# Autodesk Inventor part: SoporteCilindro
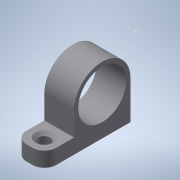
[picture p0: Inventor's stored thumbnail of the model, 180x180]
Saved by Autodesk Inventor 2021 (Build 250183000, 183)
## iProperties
Created: 2021-02
Part Number: SoporteCilindro
Material: Genérico
Document SubType Name: Modeling
Designer: ATOUZA
Density: 1 g/cm^3
Appearance: Valor por defecto
Author: ATOUZA
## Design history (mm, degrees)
sketch "Boceto1"
  geometry: L1 (4.21, 9.241)-(7.675, 15.241) reference; L2 (-2.718, 9.241)-(4.21, 9.241) reference; L3 (-9.646, 9.241)-(-2.718, 9.241) reference; L4 (-13.11, 15.241)-(-9.646, 9.241) reference; L5 (-16.574, 21.241)-(-13.11, 15.241) reference; L6 (-13.11, 27.241)-(-16.574, 21.241) reference; L7 (-9.646, 33.241)-(-13.11, 27.241) reference; L8 (-2.718, 33.241)-(-9.646, 33.241) reference; L9 (4.21, 33.241)-(-2.718, 33.241) reference; L10 (7.675, 27.241)-(4.21, 33.241) reference; L11 (11.139, 21.241)-(7.675, 27.241) reference; L12 (7.675, 15.241)-(11.139, 21.241) reference; L13 (-13.568, 35.333)-(-13.568, 39.333) reference; L14 (-15.568, 135.266)-(-15.568, 5.822); L15 (-2.718, 30.741)-(-15.568, 30.741); L16 (-2.718, 11.741)-(-15.568, 11.741); L17 (-15.568, 30.741)-(-15.568, 11.741); C1 r 8 at (-2.718, 21.241) reference; C2 r 3 at (-2.718, 21.241) reference; C3 r 3 at (-2.718, 21.241); C4 r 8.1 at (-2.718, 21.241); A1 r 9.5 centre (-2.718, 21.241) between (-2.718, 11.741) and (-2.718, 30.741); 1 further point
  constraints: 8 end point, 3 centre point, 3 coincident, 2 perpendicular, 2 point on circle, 2 point on line, 2 tangent, 2 vertical, 1 concentric
  dimensions: "d0" = 16.2 diameter of C4; "d1" = 19 diameter of A1
extrude "Extrusión1" new body sketch "Boceto1" distance "d2" = 10; taper "d3" = 0 deg
sketch "Boceto2"
  geometry: L1 (0, 0)-(10, 0) reference; L2 (10, 12.85)-(10, 0) reference; L3 (0, 0)-(10, 0); L4 (10, 0)-(10, 5); L5 (10, 5)-(0, 5); L6 (0, 5)-(0, 0); 1 further point
  constraints: 8 end point, 2 parallel, 1 horizontal, 1 perpendicular, 1 point on line
  dimensions: "d4" = 5 distance of L4.end L3.end
extrude "Extrusión2" join sketch "Boceto2" distance "d5" = 10; taper "d6" = 0 deg
fillet "Empalme1" dims "d7" = 4
sketch "Boceto3"
  geometry: L1 (0, 0)-(10, 0) reference; L2 (0, 0)-(0, -6) reference; L3 (6, -10)-(4, -10) reference; L4 (10, 0)-(10, -6) reference; L5 (0, 0)-(10, 0) reference; L6 (5, 0)-(5, -10); L7 (4, -10)-(6, -10) reference; L8 (5, -5)-(10, -5); L9 (10, 19)-(10, -6) reference; 2 further points
  constraints: 4 end point, 3 midpoint, 1 coincident, 1 perpendicular, 1 point on line
hole "Agujero1" sketch "Boceto3" at (5, -5) diameter "d8" = 4; stored, may be unused: countersink angle "d12" = 90 deg, drill point angle "d14" = 118 deg; dims "d9" = 6, "d10" = 6, "d11" = 2, "d13" = 8
sketch "Boceto4"
  geometry: 1 further point
sketch "Boceto5"
  geometry: L1 (0, 5)-(-10, 5) reference; L2 (0, 0)-(-10, 0); L3 (-10, 0)-(-10, 5); L4 (-10, 5)-(0, 5); L5 (0, 5)-(0, 0); 2 further points
  constraints: 8 end point, 2 parallel, 1 horizontal, 1 perpendicular
extrude "Extrusión3" join sketch "Boceto5" distance "d15" = 10; taper "d16" = 0 deg
fillet "Empalme2" dims "d17" = 4
sketch "Boceto6"
  geometry: L1 (0, 0)-(10, 0) reference; L2 (5, 0)-(5, 10); L3 (4, 10)-(6, 10) reference; 2 further points
  constraints: 4 midpoint, 2 end point
hole "Agujero2" sketch "Boceto6" at (5, 5) diameter "d18" = 4; stored, may be unused: countersink angle "d22" = 90 deg, drill point angle "d24" = 118 deg; dims "d19" = 6, "d20" = 6, "d21" = 2, "d23" = 8
node "Sólido1"
node "Referencia5"
node "Referencia6"
node "Referencia7"
node "Referencia8"
node "Referencia9"
node "Referencia10"
node "Referencia11"
node "Referencia12"
node "Referencia13"
node "Referencia14"
node "Referencia15"
node "Referencia16"
node "Referencia17"
node "Referencia18"
node "Referencia19"
